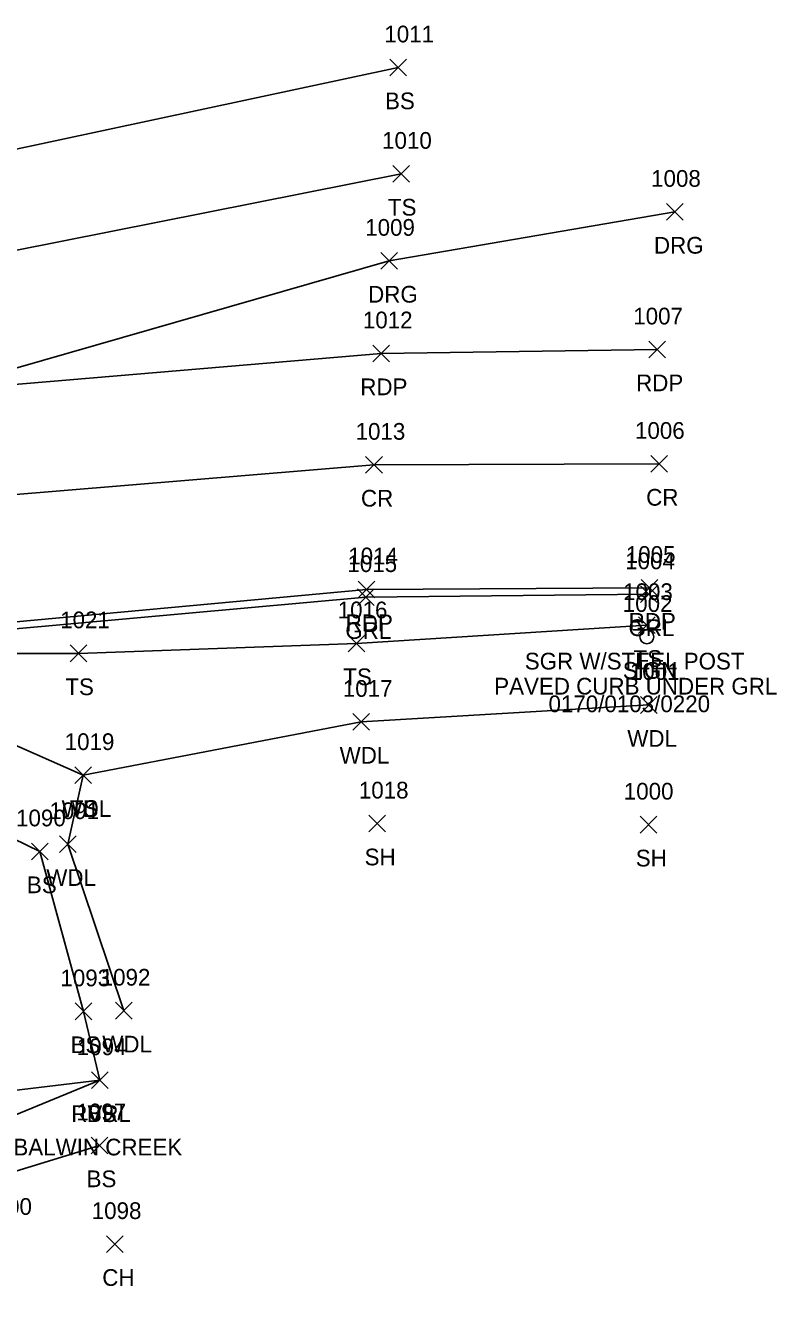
# Model space of a CAD drawing. Extents: x 1502119 to 1504100, y 606168 to 606406.
# Drawn here: x 1504009.8 to 1504099.7, y 606235.8 to 606387.9 of the extents above; entities that cross this region are included whole.
import ezdxf

# ---------------------------------------------------------------- set-up
doc = ezdxf.new("R2010")
doc.units = 0
for name, color, linetype in [('L_A', 7, 'Continuous'), ('L_C', 7, 'Continuous'), ('L_I', 7, 'Continuous'), ('L_TIC', 7, 'Continuous'), ('LAWA', 7, 'Continuous'), ('LAWE', 7, 'Continuous'), ('LELB', 7, 'Continuous'), ('P_A', 7, 'Continuous'), ('P_I', 7, 'Continuous'), ('P_TIC', 7, 'Continuous'), ('PET', 7, 'Continuous'), ('PRC', 7, 'Continuous'), ('R_A', 7, 'Continuous'), ('R_C', 7, 'Continuous'), ('R_I', 7, 'Continuous'), ('R_TIC', 7, 'Continuous'), ('RDG', 7, 'Continuous'), ('RGR', 7, 'Continuous'), ('S_A', 7, 'Continuous'), ('S_C', 7, 'Continuous'), ('S_I', 7, 'Continuous'), ('SSGN', 7, 'Continuous')]:
    doc.layers.add(name, color=color, linetype=linetype)

msp = doc.modelspace()

# ---------------------------------------------------------------- linework, layer by layer
at = {"layer": 'L_TIC'}
for points in [[(1504053.41, 606381.91), (1504055.41, 606383.91)], [(1504055.41, 606381.91), (1504053.41, 606383.91)], [(1504053.79, 606369.18), (1504055.79, 606371.18)], [(1504055.79, 606369.18), (1504053.79, 606371.18)], [(1504083.2, 606315.18), (1504085.2, 606317.18)], [(1504085.2, 606315.18), (1504083.2, 606317.18)], [(1504048.45, 606312.99), (1504050.45, 606314.99)], [(1504050.45, 606312.99), (1504048.45, 606314.99)], [(1504015.18, 606311.8), (1504017.18, 606313.8)], [(1504017.18, 606311.8), (1504015.18, 606313.8)], [(1504083.44, 606305.62), (1504085.44, 606307.62)], [(1504085.44, 606305.62), (1504083.44, 606307.62)], [(1504049.01, 606303.6), (1504051.01, 606305.6)], [(1504051.01, 606303.6), (1504049.01, 606305.6)], [(1504015.73, 606297.23), (1504017.73, 606299.23)], [(1504017.73, 606297.23), (1504015.73, 606299.23)], [(1504015.73, 606297.23), (1504017.73, 606299.23)], [(1504017.73, 606297.23), (1504015.73, 606299.23)], [(1504050.92, 606291.43), (1504052.92, 606293.43)], [(1504052.92, 606291.43), (1504050.92, 606293.43)], [(1504083.37, 606291.3), (1504085.37, 606293.3)], [(1504085.37, 606291.3), (1504083.37, 606293.3)], [(1504013.9, 606288.97), (1504015.9, 606290.97)], [(1504015.9, 606288.97), (1504013.9, 606290.97)], [(1504010.54, 606288.1), (1504012.54, 606290.1)], [(1504012.54, 606288.1), (1504010.54, 606290.1)], [(1504015.78, 606268.96), (1504017.78, 606270.96)], [(1504017.78, 606268.96), (1504015.78, 606270.96)], [(1504020.59, 606269.04), (1504022.59, 606271.04)], [(1504022.59, 606269.04), (1504020.59, 606271.04)], [(1504017.73, 606260.72), (1504019.73, 606262.72)], [(1504019.73, 606260.72), (1504017.73, 606262.72)], [(1504017.73, 606260.72), (1504019.73, 606262.72)], [(1504019.73, 606260.72), (1504017.73, 606262.72)], [(1504017.69, 606252.92), (1504019.69, 606254.92)], [(1504019.69, 606252.92), (1504017.69, 606254.92)], [(1504019.52, 606241.11), (1504021.52, 606243.11)], [(1504021.52, 606241.11), (1504019.52, 606243.11)]]:
    msp.add_lwpolyline(points, dxfattribs=at)
at = {"layer": 'LAWA'}
msp.add_lwpolyline([(1504084.44, 606306.62), (1504050.01, 606304.6), (1504016.73, 606298.23), (1504014.9, 606289.97), (1504021.59, 606270.04)], dxfattribs=at)
at = {"layer": 'LAWE'}
msp.add_lwpolyline([(1504018.73, 606261.72), (1504005.8, 606256.42), (1503986.09, 606250.69), (1503971.36, 606247.09), (1503950.87, 606245.43), (1503943.31, 606248.26), (1503934.31, 606243.71)], dxfattribs=at)
at = {"layer": 'LELB'}
for points in [[(1504054.41, 606382.91), (1503995.43, 606370.31), (1503970.29, 606365.75), (1503957.66, 606352.07), (1503951.81, 606341.47)], [(1504054.79, 606370.18), (1503996.69, 606358.67), (1503972.76, 606361.65), (1503963.87, 606349.96), (1503956.53, 606341.41), (1503954.72, 606340.41), (1503948.8, 606340.02), (1503945.63, 606339.72), (1503928.35, 606336.28), (1503910.71, 606333.69)], [(1504084.2, 606316.18), (1504049.45, 606313.99), (1504016.18, 606312.8), (1504000.76, 606312.78), (1503990.22, 606311.65), (1503980.1, 606310.35), (1503956.75, 606307.04), (1503915.14, 606300.95), (1503869.77, 606289.77), (1503847.82, 606285.43), (1503820.78, 606281.87), (1503792.45, 606279.04), (1503767.54, 606276.84), (1503743.42, 606274.71), (1503718.48, 606272.4), (1503713.68, 606272.36), (1503654.98, 606271.32), (1503649.47, 606271.35), (1503622.06, 606272.76), (1503601.12, 606274.82)], [(1504016.73, 606298.23), (1504003.23, 606304.17), (1503993.35, 606301.91), (1503983, 606300.37), (1503956.25, 606301.46), (1503922.72, 606291.41)], [(1503954.81, 606287.72), (1503972.74, 606291.05), (1503990.82, 606291.56), (1504003.55, 606292.94), (1504011.54, 606289.1), (1504016.78, 606269.96), (1504018.73, 606261.72), (1504006.07, 606260.2), (1503984.83, 606255.06)], [(1504018.69, 606253.92), (1504006.05, 606250.04), (1503985.73, 606245.35), (1503970.47, 606243.27), (1503954.82, 606236.5), (1503944.68, 606239.32), (1503929.55, 606235.83)]]:
    msp.add_lwpolyline(points, dxfattribs=at)
at = {"layer": 'P_TIC'}
for points in [[(1504051.4, 606347.69), (1504053.4, 606349.69)], [(1504053.4, 606347.69), (1504051.4, 606349.69)], [(1504084.41, 606348.16), (1504086.41, 606350.16)], [(1504086.41, 606348.16), (1504084.41, 606350.16)], [(1504050.53, 606334.36), (1504052.53, 606336.36)], [(1504052.53, 606334.36), (1504050.53, 606336.36)], [(1504084.68, 606334.47), (1504086.68, 606336.47)], [(1504086.68, 606334.47), (1504084.68, 606336.47)], [(1504049.65, 606319.45), (1504051.65, 606321.45)], [(1504051.65, 606319.45), (1504049.65, 606321.45)], [(1504083.52, 606319.63), (1504085.52, 606321.63)], [(1504085.52, 606319.63), (1504083.52, 606321.63)]]:
    msp.add_lwpolyline(points, dxfattribs=at)
at = {"layer": 'PET'}
for points in [[(1504085.41, 606349.16), (1504052.4, 606348.69), (1503999.05, 606344.18), (1503952.76, 606337.92), (1503910.76, 606332.19), (1503862.06, 606324.66), (1503811.74, 606316.76), (1503760.3, 606309.68), (1503710.83, 606303.94), (1503662.2, 606301.66), (1503623.65, 606303.36), (1503601.52, 606305.18)], [(1504084.52, 606320.63), (1504050.65, 606320.45), (1504000.43, 606315.8), (1503956.16, 606310.12), (1503915.05, 606304.21), (1503867.85, 606296.91), (1503814.4, 606288.86), (1503766.38, 606281.21), (1503714.75, 606276.43), (1503655.34, 606274.1), (1503622.19, 606275.72), (1503601.58, 606277.52)]]:
    msp.add_lwpolyline(points, dxfattribs=at)
at = {"layer": 'PRC'}
msp.add_lwpolyline([(1504085.68, 606335.47), (1504051.53, 606335.36), (1503999.5, 606331.04), (1503953.49, 606324.86), (1503912.24, 606318.81), (1503865.3, 606311.74), (1503812.8, 606303.34), (1503763.88, 606296.53), (1503711.85, 606290.88), (1503656.36, 606289.42), (1503622.63, 606290.92), (1503602.08, 606292.63)], dxfattribs=at)
at = {"layer": 'R_TIC'}
for points in [[(1504086.55, 606364.63), (1504088.55, 606366.63)], [(1504088.55, 606364.63), (1504086.55, 606366.63)], [(1504052.34, 606358.77), (1504054.34, 606360.77)], [(1504054.34, 606358.77), (1504052.34, 606360.77)], [(1504083.44, 606318.87), (1504085.44, 606320.87)], [(1504085.44, 606318.87), (1504083.44, 606320.87)], [(1504049.55, 606318.53), (1504051.55, 606320.53)], [(1504051.55, 606318.53), (1504049.55, 606320.53)]]:
    msp.add_lwpolyline(points, dxfattribs=at)
at = {"layer": 'RDG'}
msp.add_lwpolyline([(1504087.55, 606365.63), (1504053.34, 606359.77), (1503999.05, 606344.18)], dxfattribs=at)
at = {"layer": 'RGR'}
msp.add_lwpolyline([(1504084.44, 606319.87), (1504050.55, 606319.53), (1504000.64, 606315), (1503956.05, 606309.11), (1503915.05, 606302.99), (1503867.97, 606295.96), (1503814.82, 606287.72), (1503766.2, 606280.53), (1503714.79, 606275.76), (1503655.19, 606273.62), (1503622.1, 606275.05), (1503601.6, 606277)], dxfattribs=at)
at = {"layer": 'SSGN'}
for p, q in [((1504082.53, 606315.61), (1504085.86, 606315.61)), ((1504084.18, 606314.78), (1504084.18, 606314.78))]:
    msp.add_line(p, q, dxfattribs=at)
msp.add_circle((1504084.18, 606314.78), 0.833, dxfattribs=at)

# ---------------------------------------------------------------- texts
at = {"layer": 'L_A'}
for s, p in [('BS', (1504052.85, 606377.91)), ('TS', (1504053.2, 606365.18)), ('TS', (1504082.61, 606311.18)), ('TS', (1504047.86, 606308.99)), ('TS', (1504014.59, 606307.8)), ('WDL', (1504081.85, 606301.62)), ('WDL', (1504047.42, 606299.6)), ('WDL', (1504014.14, 606293.23)), ('TS', (1504015.13, 606293.23)), ('SH', (1504050.41, 606287.43)), ('SH', (1504082.86, 606287.3)), ('BS', (1504009.99, 606284.1)), ('WDL', (1504012.31, 606284.97)), ('BS', (1504015.22, 606264.96)), ('WDL', (1504019.01, 606265.04)), ('RVRL', (1504015.3, 606256.72)), ('BS', (1504017.17, 606256.72)), ('BS', (1504017.13, 606248.92)), ('CH', (1504019.01, 606237.11))]:
    msp.add_text(s, height=2, dxfattribs=at).set_placement(p)
at = {"layer": 'L_C'}
msp.add_text('BALWIN CREEK', height=2, dxfattribs=at).set_placement((1504008.37, 606252.72))
at = {"layer": 'L_I'}
for s, p in [('1011', (1504052.77, 606385.91)), ('1010', (1504052.5, 606373.18)), ('1003', (1504081.35, 606319.18)), ('1016', (1504047.19, 606316.99)), ('1021', (1504013.97, 606315.8)), ('1001', (1504082.15, 606309.62)), ('1017', (1504047.8, 606307.6)), ('1019', (1504014.51, 606301.23)), ('1019', (1504014.51, 606301.23)), ('1018', (1504049.72, 606295.43)), ('1000', (1504081.43, 606295.3)), ('1091', (1504012.69, 606292.97)), ('1090', (1504008.69, 606292.1)), ('1093', (1504014, 606272.96)), ('1092', (1504018.82, 606273.04)), ('1094', (1504015.96, 606264.72)), ('1094', (1504015.96, 606264.72)), ('1097', (1504015.92, 606256.92)), ('1100', (1504004.64, 606245.61)), ('1098', (1504017.75, 606245.11))]:
    msp.add_text(s, height=2, dxfattribs=at).set_placement(p)
at = {"layer": 'P_A'}
for s, p in [('RDP', (1504049.89, 606343.69)), ('RDP', (1504082.9, 606344.16)), ('CR', (1504049.97, 606330.36)), ('CR', (1504084.11, 606330.47)), ('RDP', (1504082.01, 606315.63)), ('RDP', (1504048.14, 606315.45))]:
    msp.add_text(s, height=2, dxfattribs=at).set_placement(p)
at = {"layer": 'P_I'}
for s, p in [('1007', (1504082.56, 606352.16)), ('1012', (1504050.2, 606351.69)), ('1013', (1504049.33, 606338.36)), ('1006', (1504082.77, 606338.47)), ('1014', (1504048.45, 606323.45)), ('1005', (1504081.67, 606323.63))]:
    msp.add_text(s, height=2, dxfattribs=at).set_placement(p)
at = {"layer": 'R_A'}
for s, p in [('DRG', (1504085.04, 606360.63)), ('DRG', (1504050.83, 606354.77)), ('GRL', (1504048.1, 606314.53)), ('GRL', (1504081.99, 606314.87))]:
    msp.add_text(s, height=2, dxfattribs=at).set_placement(p)
at = {"layer": 'R_C'}
for s, p in [('SGR W/STEEL POST', (1504069.58, 606310.87)), ('PAVED CURB UNDER GRL', (1504065.92, 606307.87))]:
    msp.add_text(s, height=2, dxfattribs=at).set_placement(p)
at = {"layer": 'R_I'}
for s, p in [('1008', (1504084.7, 606368.63)), ('1009', (1504050.48, 606362.77)), ('1015', (1504048.35, 606322.53)), ('1004', (1504081.59, 606322.87))]:
    msp.add_text(s, height=2, dxfattribs=at).set_placement(p)
at = {"layer": 'S_A'}
msp.add_text('SIGN', height=2, dxfattribs=at).set_placement((1504081.31, 606309.76))
at = {"layer": 'S_C'}
msp.add_text('0170/0103/0220', height=2, dxfattribs=at).set_placement((1504072.42, 606305.76))
at = {"layer": 'S_I'}
msp.add_text('1002', height=2, dxfattribs=at).set_placement((1504081.31, 606317.76))

doc.saveas('drawing.dxf')
